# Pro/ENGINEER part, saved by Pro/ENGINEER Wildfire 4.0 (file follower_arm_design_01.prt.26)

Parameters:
  METRIC = "NO"

Other parameters: PITCH, DRILL_DIAMETER, THREAD_DIAMETER, THREADS_PER_INCH, THREAD_DEPTH, THREAD_LENGTH, DRILL_POINT_ANGLE, DRILL_DEPTH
